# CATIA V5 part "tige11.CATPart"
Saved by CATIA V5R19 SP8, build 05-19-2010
Part number: tige11
Bounding box of the stored display mesh (mm): x -51.631 to -46.631, y 103.055 to 182.656, z -23.48 to 59.511
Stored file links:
  G:\EU_thinkMotion\CFAO_2010\MMS_groupe2\MMS_groupe2\A reprendre\jcauchy\tige11.CATPart
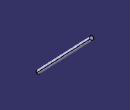
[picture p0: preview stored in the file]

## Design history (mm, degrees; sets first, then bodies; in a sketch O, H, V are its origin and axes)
Parameters
  Longueurtige_tige11 = 110 mm
  Rayontige_tige11 = 5 mm
Set1
  Plane1: stored without definition
  Sketch1 on Plane1, origin (0, 115.1599, 120.5405), H (1, 0, 0), V (0, -0.7231, 0.6908)
    circle A1 centre (-49.1308, -90.8483) radius 2.5
    radius A1 = 2.5 {= Rayontige_tige11 /2}
Body1 (main body)
  Pad1: profile Sketch1, direction (0, -0.6908, -0.7231), length 110 {= Longueurtige_tige11}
